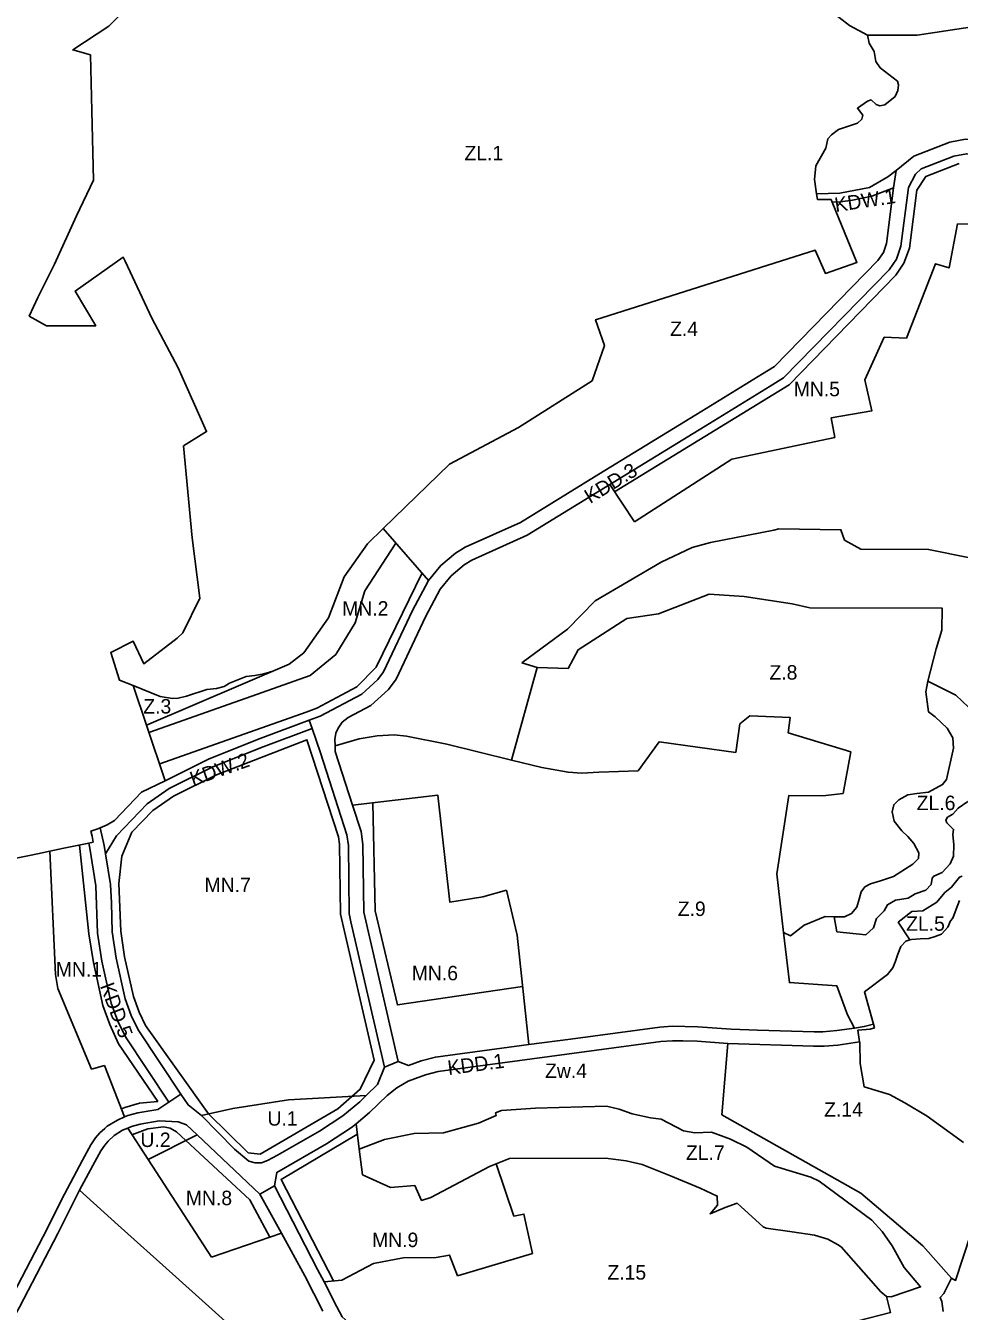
# Model space of a CAD drawing. Extents: x 7425478 to 7427982, y 5538517 to 5541171.
# Drawn here: x 7426136 to 7426780, y 5539827 to 5540715 of the extents above; entities that cross this region are included whole.
import ezdxf

# ---------------------------------------------------------------- set-up
doc = ezdxf.new("R2010")
doc.units = 0
for name, color, linetype in [('linie_rozgraniczajace', 7, 'Continuous'), ('linie_zabudowy_nieprzekraczalne', 7, 'Continuous'), ('oznaczenia_przeznaczen', 7, 'Continuous')]:
    doc.layers.add(name, color=color, linetype=linetype)

msp = doc.modelspace()

# ---------------------------------------------------------------- linework, layer by layer
at = {"layer": 'linie_rozgraniczajace'}
for p, q in [((7426731.05, 5540610.84), (7426736.88, 5540615.14)), ((7426736.88, 5540615.14), (7426735.09, 5540603.21)), ((7426539.11, 5540398.25), (7426556.16, 5540372.49)), ((7426382.66, 5540367.98), (7426413.98, 5540332.1)), ((7426317.69, 5540274.2), (7426219.13, 5540232.16)), ((7426488.83, 5540271.89), (7426471.19, 5540207.93)), ((7426331.51, 5540235.5), (7426333.49, 5540229.81)), ((7426383.59, 5539995.88), (7426392.95, 5539999.8)), ((7426242.88, 5539977.24), (7426234.54, 5539971.71)), ((7426365.94, 5539939.15), (7426363.89, 5539956.79)), ((7426254, 5539949.12), (7426297.44, 5539908.12)), ((7426220.18, 5539932.05), (7426263.89, 5539864.55)), ((7426297.44, 5539908.12), (7426307.41, 5539913.93)), ((7426263.89, 5539864.55), (7426312.26, 5539881.08))]:
    msp.add_line(p, q, dxfattribs=at)
for points in [[(7426717.2, 5540708.68), (7426751.28, 5540708.68), (7426790.92, 5540714.76), (7426810.72, 5540713.06), (7426828.41, 5540705.75), (7426867.84, 5540713.85), (7426908.44, 5540725.51), (7426925.27, 5540731.18), (7426935.28, 5540732.24), (7426974.9, 5540738.42), (7427001.7, 5540742.96), (7427027.17, 5540753.71), (7427042.19, 5540761.09), (7427056.12, 5540769.24), (7427073.04, 5540767.39)], [(7426114.72, 5540137.37), (7426139.34, 5540142.21), (7426147.09, 5540143.92), (7426152.34, 5540145.07), (7426162.05, 5540147.21), (7426179.19, 5540150.67), (7426182.18, 5540151.27), (7426181.63, 5540155.28), (7426180.71, 5540158.94), (7426184.79, 5540160.14), (7426187.14, 5540161.15), (7426191.85, 5540163.18), (7426197.03, 5540166.18), (7426215.67, 5540185.86), (7426232.11, 5540193.68), (7426219.13, 5540232.16), (7426209.94, 5540259.4), (7426200.43, 5540263.25), (7426194.41, 5540282.31), (7426209.98, 5540290), (7426217.22, 5540274.54), (7426240.22, 5540292.2), (7426244.2, 5540295.77), (7426256.04, 5540319.86), (7426250.65, 5540361.46), (7426244.6, 5540424.97), (7426260.61, 5540434.84), (7426241.03, 5540478.97), (7426222.9, 5540513.19), (7426204.34, 5540552.54), (7426202.99, 5540555.41), (7426169.88, 5540531.97), (7426184.03, 5540507.92), (7426150.11, 5540507.96), (7426138.09, 5540514.63), (7426144.07, 5540527.39), (7426155.6, 5540550.57), (7426170.85, 5540583.91), (7426182.53, 5540608.45), (7426181.33, 5540656.47), (7426180.4, 5540695.04), (7426168.21, 5540698.49), (7426193.17, 5540714.88), (7426220.04, 5540742.49)], [(7426621, 5540724.8), (7426690.34, 5540726.34), (7426704.54, 5540715.43), (7426717.2, 5540708.68)], [(7426717.2, 5540708.68), (7426718.28, 5540703.16), (7426721.58, 5540697.31), (7426722.91, 5540690.52), (7426725.83, 5540686.18), (7426737.82, 5540676.86), (7426738.6, 5540674.32), (7426738.02, 5540670.5), (7426736.1, 5540666.31), (7426729.04, 5540660.65), (7426725.66, 5540659.96)], [(7426681.93, 5540599.19), (7426680.54, 5540609.03), (7426681.47, 5540618.54), (7426688.22, 5540630.74), (7426689.69, 5540636.98), (7426692.12, 5540639.96), (7426697.09, 5540643.46), (7426710.13, 5540647.86), (7426713.14, 5540650.73), (7426713.9, 5540653.51), (7426710.17, 5540658.26), (7426717.16, 5540663.2), (7426719.71, 5540663.97), (7426723.13, 5540660.82), (7426725.66, 5540659.96)], [(7426816.94, 5540628.58), (7426806.42, 5540633.45), (7426794.75, 5540636.3), (7426784.82, 5540636.93), (7426773.93, 5540634.87), (7426749.1, 5540625.08), (7426736.88, 5540615.14)], [(7426539.11, 5540398.25), (7426541.43, 5540399.68), (7426607.94, 5540440.48), (7426649.9, 5540466.22), (7426659.15, 5540471.89), (7426732.05, 5540546.65), (7426737.1, 5540553.97), (7426740.18, 5540562.9), (7426745.32, 5540603.54), (7426750.19, 5540612.79), (7426754.12, 5540616.34), (7426776.71, 5540625.22), (7426785.4, 5540626.76), (7426793.22, 5540626.29), (7426803.14, 5540623.95), (7426814.99, 5540618.47), (7426820.42, 5540614.61), (7426825.48, 5540609.63)], [(7426681.93, 5540599.19), (7426697.96, 5540599.45), (7426718.4, 5540603.37), (7426731.05, 5540610.84)], [(7426825.48, 5540609.63), (7426812.98, 5540577.96), (7426779.26, 5540578.26), (7426773.48, 5540547.95), (7426764.01, 5540550.84), (7426743.97, 5540499.31)], [(7426735.09, 5540603.21), (7426730.23, 5540564.71), (7426728.1, 5540558.53), (7426724.3, 5540553.02), (7426652.86, 5540479.76), (7426644.67, 5540474.74), (7426602.71, 5540449), (7426531.43, 5540405.35)], [(7426692.75, 5540593.37), (7426691.9, 5540595.15), (7426682.56, 5540595.15), (7426681.93, 5540599.19)], [(7426692.75, 5540593.37), (7426698.49, 5540593.46), (7426706.73, 5540594.8), (7426720.09, 5540597.59), (7426735.09, 5540603.21)], [(7426476.02, 5540437.68), (7426526.86, 5540469.97), (7426535.4, 5540494.44), (7426529.3, 5540512.1), (7426680.91, 5540560.2), (7426688.01, 5540544.1), (7426709.74, 5540551.68), (7426692.75, 5540593.37)], [(7426743.97, 5540499.31), (7426728.69, 5540500.04), (7426715.14, 5540470.66), (7426720.03, 5540449.11), (7426692.04, 5540444.35), (7426694.47, 5540430.69)], [(7426382.66, 5540367.98), (7426428.37, 5540412.39), (7426476.02, 5540437.68)], [(7426694.47, 5540430.69), (7426623.43, 5540415.8), (7426556.16, 5540372.49)], [(7426531.43, 5540405.35), (7426477.4, 5540372.14), (7426439.1, 5540354.99), (7426432.57, 5540350.95), (7426422.47, 5540342.35), (7426413.98, 5540332.1)], [(7426349.32, 5540217.73), (7426349.12, 5540222.2), (7426349.89, 5540226.48), (7426351.55, 5540230), (7426354.25, 5540234.1), (7426358.49, 5540237.46), (7426374.07, 5540245.76), (7426386.35, 5540256.79), (7426391.48, 5540263.83), (7426411.79, 5540306.93), (7426421.92, 5540326.01), (7426429.61, 5540335.3), (7426438.48, 5540342.84), (7426443.8, 5540346.14), (7426482.08, 5540363.27), (7426539.11, 5540398.25)], [(7426876.56, 5540376.66), (7426815.24, 5540342.11), (7426759.33, 5540353.52), (7426712.55, 5540353.68), (7426701.1, 5540359.93), (7426698.75, 5540367.01), (7426655.83, 5540367.75), (7426652.37, 5540366.73), (7426608.69, 5540358.29), (7426595.99, 5540354.73), (7426574.58, 5540344.68), (7426528.94, 5540317.84), (7426509.87, 5540298.47), (7426478.31, 5540275.12)], [(7426317.69, 5540274.2), (7426327.75, 5540282), (7426344.73, 5540306.26), (7426355.53, 5540334.51), (7426371.82, 5540357.44), (7426382.66, 5540367.98)], [(7426413.98, 5540332.1), (7426413.56, 5540331.59), (7426402.75, 5540311.19), (7426382.84, 5540268.95), (7426378.8, 5540263.58), (7426367.78, 5540253.55), (7426339.15, 5540238.33), (7426331.51, 5540235.5)], [(7426488.83, 5540271.89), (7426510.33, 5540271.12), (7426517.33, 5540284.21), (7426550.85, 5540305.65), (7426572.85, 5540309), (7426607.75, 5540322.65), (7426631.95, 5540320.84), (7426665.02, 5540315.84), (7426677.19, 5540313.17), (7426768.65, 5540312.95), (7426768.37, 5540297.72), (7426764.51, 5540284.7), (7426758.79, 5540262.45)], [(7426209.94, 5540259.4), (7426228.62, 5540251.82), (7426237.16, 5540250.45), (7426241.05, 5540250.8), (7426246.82, 5540252.09), (7426260.8, 5540256.71), (7426267.37, 5540257.34), (7426272.79, 5540258.87), (7426276.45, 5540261.02), (7426288, 5540265.64), (7426293.88, 5540266.29), (7426300.16, 5540267.56), (7426306.37, 5540269.47), (7426317.69, 5540274.2)], [(7426478.31, 5540275.12), (7426488.83, 5540271.89)], [(7426758.79, 5540262.45), (7426757.4, 5540255.05), (7426759.28, 5540241.19), (7426763.85, 5540237.93), (7426772.09, 5540230.09), (7426776.07, 5540223.24), (7426776.38, 5540216.18), (7426771.54, 5540194.56), (7426768.89, 5540191.01), (7426759.29, 5540185.8), (7426751.09, 5540184.91), (7426744.98, 5540183.93), (7426738.79, 5540180.58), (7426735.21, 5540177.09), (7426734.2, 5540172.25), (7426735.6, 5540165.74), (7426740.85, 5540158.98), (7426744.97, 5540155.21), (7426749.02, 5540150.33), (7426752.47, 5540143.84), (7426752.23, 5540140.04), (7426748.51, 5540136.1), (7426734.99, 5540127.56), (7426726.07, 5540124.49), (7426719.09, 5540122.45), (7426715.16, 5540120.35), (7426712.71, 5540117.03), (7426711.32, 5540111.85), (7426709.7, 5540106.43), (7426706.13, 5540101.96), (7426701.11, 5540099.68), (7426694.07, 5540099.6)], [(7426786.93, 5540244.43), (7426778.12, 5540252.72), (7426758.79, 5540262.45)], [(7426232.11, 5540193.68), (7426262.47, 5540208.82), (7426297.58, 5540222.79), (7426331.51, 5540235.5)], [(7426626.08, 5540213.11), (7426628.97, 5540232.89), (7426635.83, 5540238.56), (7426663.77, 5540237.34), (7426662.34, 5540226.66)], [(7426190.73, 5540143.14), (7426198.36, 5540155.68), (7426219.49, 5540177.8), (7426234.79, 5540188.31), (7426264.93, 5540203.34), (7426299.68, 5540217.17), (7426333.49, 5540229.81)], [(7426333.49, 5540229.81), (7426339.24, 5540213.01), (7426357.48, 5540156.31), (7426358.56, 5540148.94), (7426359.17, 5540102.06), (7426360.15, 5540096.27), (7426383.59, 5539995.88)], [(7426659.11, 5540088.9), (7426654.41, 5540129.36), (7426662.86, 5540183.51), (7426686.15, 5540183.25), (7426700.21, 5540184.88), (7426705.54, 5540213.54), (7426662.34, 5540226.66)], [(7426426.51, 5540218.94), (7426398.64, 5540224.49), (7426390.26, 5540225.33), (7426378.48, 5540224.77), (7426366.06, 5540222.71), (7426349.32, 5540217.73)], [(7426349.32, 5540217.73), (7426349.5, 5540213.77), (7426361.42, 5540176.73)], [(7426426.51, 5540218.94), (7426471.19, 5540207.93)], [(7426626.08, 5540213.11), (7426573.14, 5540220.5), (7426558.62, 5540200.41)], [(7426471.19, 5540207.93), (7426492.24, 5540202.74), (7426510.24, 5540199.57), (7426519.84, 5540198.88), (7426531.43, 5540199.51), (7426558.62, 5540200.41)], [(7426361.42, 5540176.73), (7426420.37, 5540183.64), (7426428.5, 5540109.83), (7426451.37, 5540113.45), (7426467.84, 5540118.15)], [(7426361.42, 5540176.73), (7426367.26, 5540158.58), (7426368.55, 5540149.73), (7426369.16, 5540102.96), (7426392.95, 5539999.8)], [(7426694.07, 5540099.6), (7426695.96, 5540089.41), (7426715.91, 5540087.19), (7426721.22, 5540091.99), (7426723.41, 5540098.55), (7426728.6, 5540103.7), (7426730.99, 5540108.03), (7426736.42, 5540111.13), (7426745.19, 5540112.45), (7426749.96, 5540115.46), (7426757.3, 5540118.04), (7426761.14, 5540122.08), (7426761.79, 5540126.47), (7426762.9, 5540127.82), (7426768.59, 5540130.39), (7426774.15, 5540136.35), (7426776.51, 5540141.63), (7426776.76, 5540149.3), (7426775.96, 5540156.6), (7426776.56, 5540160.11), (7426771.84, 5540164.51), (7426771.22, 5540166.4), (7426772.23, 5540168.44), (7426776.07, 5540170.69), (7426779.66, 5540174.68), (7426786.36, 5540179.24)], [(7426187.14, 5540161.15), (7426189.79, 5540149), (7426190.73, 5540143.14)], [(7426179.19, 5540150.67), (7426179.96, 5540147.14), (7426184.19, 5540121.01), (7426185.21, 5540088.4), (7426188.29, 5540069.14), (7426194.77, 5540040.12), (7426199.34, 5540027.54), (7426204.68, 5540016.71), (7426234.54, 5539971.71)], [(7426152.34, 5540145.07), (7426156.19, 5540059.74), (7426157.81, 5540050.14), (7426181.16, 5539994.47), (7426190.06, 5539996.87), (7426204.01, 5539961.42)], [(7426190.73, 5540143.14), (7426194.14, 5540122.1), (7426194.87, 5540109.33), (7426195.3, 5540089.29), (7426198.12, 5540071.02), (7426204.39, 5540042.93), (7426208.57, 5540031.43), (7426213.29, 5540021.63), (7426242.88, 5539977.24)], [(7426746.25, 5540083.73), (7426738.37, 5540095.96), (7426747.68, 5540103.35), (7426755.24, 5540103.81), (7426764.91, 5540109.86), (7426770.52, 5540116.42), (7426775.13, 5540120.09), (7426780.59, 5540127.08), (7426782.46, 5540127.73)], [(7426475.03, 5540087.02), (7426467.84, 5540118.15)], [(7426780.53, 5540110.98), (7426778.31, 5540104.9), (7426776.1, 5540098.83), (7426774.41, 5540096.87), (7426772.54, 5540092.44), (7426768.28, 5540087.61), (7426763.87, 5540086.14), (7426759.46, 5540084.66), (7426753.5, 5540084.38), (7426747.54, 5540084.1), (7426746.25, 5540083.73), (7426743.58, 5540082.96), (7426740.15, 5540079.11), (7426738.14, 5540073.83), (7426736.34, 5540069.08), (7426734.53, 5540064.34), (7426730.96, 5540059.83), (7426715.01, 5540047.76), (7426721.14, 5540025.56), (7426721.87, 5540022.91), (7426718.97, 5540022.01), (7426710.5, 5540021.4), (7426711.64, 5540013.23), (7426711.73, 5540012.6), (7426712.07, 5539998.44), (7426714.67, 5539982.3), (7426732.25, 5539976.93), (7426742.97, 5539971.2), (7426758.36, 5539961.98), (7426783.48, 5539943.79)], [(7426659.11, 5540088.9), (7426664.01, 5540086.51), (7426673.35, 5540093.92), (7426687.84, 5540099.88), (7426694.07, 5540099.6)], [(7426483.12, 5540011.39), (7426475.03, 5540087.02)], [(7426708.01, 5540022.82), (7426703.35, 5540032.05), (7426695.86, 5540052.07), (7426663.14, 5540054.25), (7426659.11, 5540088.9)], [(7426708.01, 5540022.82), (7426695.8, 5540021.05), (7426686.3, 5540020.31), (7426680.18, 5540020.24), (7426641.21, 5540021.45), (7426622.92, 5540022.02), (7426599.97, 5540023.75), (7426582.06, 5540024.11), (7426573.76, 5540023.53), (7426511.97, 5540015.25), (7426483.12, 5540011.39)], [(7426708.01, 5540022.82), (7426714.85, 5540023.8), (7426721.14, 5540025.56)], [(7426620.66, 5540012.17), (7426599.5, 5540013.86), (7426589.56, 5540013.96), (7426582.31, 5540014.11), (7426574.46, 5540013.56), (7426420.64, 5539992.93), (7426411.78, 5539990.57), (7426399.79, 5539986.26), (7426391.94, 5539981.61), (7426385.28, 5539976.36), (7426373.11, 5539964.44), (7426363.89, 5539956.79)], [(7426620.66, 5540012.17), (7426679.87, 5540010.25), (7426687.08, 5540010.34), (7426696.64, 5540011.09), (7426711.64, 5540013.23)], [(7426392.95, 5539999.8), (7426400.11, 5539997), (7426408.8, 5540000.12), (7426418.68, 5540002.75), (7426483.12, 5540011.39)], [(7426775.14, 5539850.04), (7426755.35, 5539872.34), (7426712.53, 5539908.71), (7426616.48, 5539962.94), (7426620.66, 5540012.17)], [(7426383.59, 5539995.88), (7426378.67, 5539983.88), (7426370.9, 5539976.28)], [(7426234.54, 5539971.71), (7426226.91, 5539966.54), (7426213.06, 5539964.26), (7426206.17, 5539962.34), (7426204.01, 5539961.42)], [(7426257.18, 5539962.39), (7426247.91, 5539969.69), (7426242.88, 5539977.24)], [(7426257.18, 5539962.39), (7426278.82, 5539967.23), (7426317.07, 5539973.35), (7426370.9, 5539976.28)], [(7426370.9, 5539976.28), (7426366.4, 5539971.87), (7426354.75, 5539962.19), (7426338.55, 5539951.51), (7426309.68, 5539935.03), (7426302.75, 5539931.29), (7426298.54, 5539929.82), (7426294.07, 5539929.79), (7426289.74, 5539930.88), (7426279.87, 5539939.17), (7426257.18, 5539962.39)], [(7426730.15, 5539837.31), (7426733.53, 5539837.14), (7426753.78, 5539844.06), (7426742.35, 5539857.36), (7426734.03, 5539872.41), (7426727.15, 5539882.39), (7426720.01, 5539890.12), (7426683.71, 5539917.05), (7426677.85, 5539919.86), (7426652.8, 5539927.48), (7426633.86, 5539940.56), (7426622.47, 5539946.19), (7426609.25, 5539951.02), (7426597.85, 5539950.45), (7426590.04, 5539951.75), (7426574.49, 5539959.84), (7426567.24, 5539960.82), (7426554.49, 5539963.5), (7426545.58, 5539966.92), (7426536.85, 5539968.81), (7426487.8, 5539967.5), (7426464.34, 5539965.93), (7426460.23, 5539964.2), (7426460.7, 5539962.46), (7426448.32, 5539957.18), (7426424.27, 5539950.4), (7426403.96, 5539949.92), (7426383.58, 5539945.97), (7426365.94, 5539939.15)], [(7426204.01, 5539961.42), (7426198.99, 5539959.27), (7426192.04, 5539954.96), (7426190.44, 5539953.51)], [(7426190.44, 5539953.51), (7426186.95, 5539950.37), (7426183.98, 5539946.92), (7426180.68, 5539942.27), (7426174.89, 5539931.6), (7426162.52, 5539908.13), (7426159.34, 5539901.8)], [(7426206.19, 5539953.65), (7426202.64, 5539952.24), (7426196.8, 5539948.62), (7426192.68, 5539944.76), (7426190.28, 5539941.98), (7426187.48, 5539938.04), (7426181.94, 5539927.82), (7426172.93, 5539910.75)], [(7426206.19, 5539953.65), (7426208.83, 5539954.77), (7426214.82, 5539956.45), (7426227.97, 5539958.7), (7426241.03, 5539958.1), (7426246.7, 5539955.97), (7426254, 5539949.12)], [(7426206.19, 5539953.65), (7426220.18, 5539932.05)], [(7426307.41, 5539913.93), (7426309.06, 5539923.16), (7426343.52, 5539942.84), (7426360.71, 5539954.14), (7426363.89, 5539956.79)], [(7426220.18, 5539932.05), (7426254, 5539949.12)], [(7426365.94, 5539939.15), (7426368.31, 5539921.53), (7426387.64, 5539912.62), (7426404.45, 5539914.05), (7426409.15, 5539903.77), (7426415.6, 5539905.73), (7426455.97, 5539927.28), (7426460.7, 5539929.11)], [(7426730.15, 5539837.31), (7426726.41, 5539840.54), (7426698.92, 5539871.65), (7426696.41, 5539873.44), (7426689.79, 5539877.12), (7426680.39, 5539879.83), (7426665.12, 5539881.98), (7426647.1, 5539884.51), (7426645.07, 5539885.5), (7426626.99, 5539901.8), (7426618.67, 5539898.87), (7426608.34, 5539894.53), (7426613.47, 5539900.46), (7426613.35, 5539906.75), (7426601.6, 5539912.15), (7426581.08, 5539920.81), (7426561.53, 5539928.63), (7426550.29, 5539931.19), (7426536.23, 5539933.02), (7426469.9, 5539932.65), (7426460.7, 5539929.11)], [(7426472.76, 5539892.84), (7426460.7, 5539929.11)], [(7426172.93, 5539910.75), (7426157.78, 5539880.88), (7426131.38, 5539829.96), (7426120.78, 5539811.26), (7426109.12, 5539796.88), (7426076.6, 5539761.74), (7426068.87, 5539756.4), (7426052.03, 5539754.96), (7426040.49, 5539757.6), (7426024.63, 5539763.12), (7426003.8, 5539773.22), (7425997.61, 5539775.55), (7425990.1, 5539777.21), (7425982.57, 5539778.07)], [(7426172.93, 5539910.75), (7426199.52, 5539886.77), (7426237.04, 5539852.97), (7426285, 5539810.09)], [(7426297.44, 5539908.12), (7426312.26, 5539881.08)], [(7426307.41, 5539913.93), (7426337.31, 5539856.17), (7426341.76, 5539847.53)], [(7425861.28, 5539789.58), (7425876.14, 5539788.48), (7425917.05, 5539790.68), (7425930.12, 5539791.21), (7425946.2, 5539790.43), (7425991.44, 5539785.11), (7425999.89, 5539783.23), (7426006.95, 5539780.58), (7426027.7, 5539770.52), (7426042.71, 5539765.3), (7426052.59, 5539763.04), (7426066.07, 5539764.19), (7426071.32, 5539767.83), (7426103.07, 5539802.12), (7426114.14, 5539815.78), (7426124.35, 5539833.77), (7426150.65, 5539884.52), (7426159.34, 5539901.8)], [(7426433.95, 5539851.74), (7426485.62, 5539867.17), (7426479.74, 5539894.35), (7426472.76, 5539892.84)], [(7426312.26, 5539881.08), (7426328.42, 5539851.59), (7426341, 5539827.19)], [(7426788.38, 5539880.66), (7426777.89, 5539848.46), (7426775.14, 5539850.04), (7426769.82, 5539839.5), (7426767.19, 5539836.75), (7426768.52, 5539834.05), (7426769.46, 5539826.99)], [(7426433.95, 5539851.74), (7426428.35, 5539866.05), (7426419.12, 5539864.37), (7426396.42, 5539864.16), (7426375.91, 5539860.18), (7426354.01, 5539848.67), (7426341.76, 5539847.53)], [(7426341.76, 5539847.53), (7426350.65, 5539830.3), (7426354.22, 5539823.36), (7426360.39, 5539817.82), (7426382.72, 5539807.31), (7426387.89, 5539805.46), (7426392.07, 5539804.68), (7426406.6, 5539801.94), (7426417.95, 5539798.68), (7426428.88, 5539791.94), (7426435.25, 5539784.9), (7426444.81, 5539772.3)], [(7426566.31, 5539790.94), (7426585.56, 5539801.43), (7426621.44, 5539806.39), (7426651.66, 5539810.88), (7426672.2, 5539814.35), (7426709.79, 5539820.37), (7426732.96, 5539826.26), (7426730.15, 5539837.31)]]:
    msp.add_lwpolyline(points, dxfattribs=at)
at = {"layer": 'linie_zabudowy_nieprzekraczalne'}
for p, q in [((7426208.97, 5540158.1), (7426202.06, 5540141.48)), ((7426219.96, 5539953.2), (7426209.08, 5539949.19))]:
    msp.add_line(p, q, dxfattribs=at)
for points in [[(7426780.48, 5540620.13), (7426757.33, 5540611.15), (7426751.14, 5540601.71), (7426746.06, 5540561.53), (7426742.15, 5540551.19), (7426736.71, 5540542.83), (7426662.92, 5540467.17), (7426542.42, 5540393.25)], [(7426391.38, 5540357.75), (7426369.89, 5540324.97), (7426363.3, 5540302.67), (7426349.95, 5540280.95), (7426332.06, 5540266.3), (7426287.87, 5540250.73), (7426220.83, 5540227.1)], [(7426228.38, 5540205.25), (7426228.38, 5540205.25), (7426329.41, 5540241.12), (7426336.69, 5540243.81), (7426364.3, 5540258.5), (7426377.67, 5540272.07), (7426409.42, 5540337.28)], [(7426202.06, 5540141.48), (7426200.11, 5540122.75), (7426201.29, 5540089.81), (7426204.02, 5540072.13), (7426210.16, 5540044.62), (7426214.1, 5540033.76), (7426218.52, 5540024.61), (7426261.84, 5539963.5), (7426289.26, 5539936.72), (7426297.5, 5539935.82), (7426351.17, 5539967.02), (7426366.7, 5539980.56), (7426376.4, 5540000.56), (7426353.18, 5540101.52), (7426352.43, 5540149.76), (7426351.62, 5540154.95), (7426329.89, 5540222.03), (7426267.38, 5540197.86), (7426237.84, 5540183.13), (7426223.4, 5540173.21), (7426208.97, 5540158.1)], [(7426375.4, 5540178.37), (7426377.15, 5540103.92), (7426392.37, 5540038.88), (7426478.83, 5540051.5)], [(7426226.96, 5539972.19), (7426199.85, 5540011.87), (7426193.81, 5540025.19), (7426189, 5540038.44), (7426182.4, 5540068.01), (7426179.23, 5540087.83), (7426172.73, 5540149.28)], [(7426201.81, 5539967), (7426204.18, 5539968.01), (7426214.35, 5539970.88), (7426226.96, 5539972.19)], [(7426304.3, 5539878.36), (7426290.42, 5539904.28), (7426239.87, 5539951.26), (7426235.48, 5539953.66), (7426230.9, 5539954.51), (7426219.96, 5539953.2)], [(7426364.29, 5539949.31), (7426312.07, 5539918.3), (7426348.21, 5539848.13)]]:
    msp.add_lwpolyline(points, dxfattribs=at)

# ---------------------------------------------------------------- texts
at = {"layer": 'oznaczenia_przeznaczen'}
for s, p in [('ZL.1', (7426438.71, 5540622.24)), ('Z.4', (7426580.72, 5540500.9)), ('MN.5', (7426666.13, 5540459.25)), ('MN.2', (7426354.26, 5540307.72)), ('Z.8', (7426649.36, 5540263.51)), ('Z.3', (7426216.87, 5540240.12)), ('ZL.6', (7426751.06, 5540173.39)), ('MN.7', (7426259.22, 5540116.71)), ('Z.9', (7426586.02, 5540100.23)), ('ZL.5', (7426743.77, 5540090.02)), ('MN.1', (7426156.49, 5540058.45)), ('MN.6', (7426402.32, 5540055.83)), ('Zw.4', (7426494.37, 5539988.34)), ('Z.14', (7426687.12, 5539961.59)), ('U.1', (7426302.7, 5539955.42)), ('U.2', (7426214.92, 5539940.66)), ('ZL.7', (7426591.66, 5539931.72)), ('MN.8', (7426246.28, 5539900.49)), ('MN.9', (7426374.87, 5539871.52)), ('Z.15', (7426537.44, 5539849.07))]:
    msp.add_text(s, height=10, dxfattribs=at).set_placement(p)
for s, rotation, p in [('KDW.1', 8.69998, (7426695.17, 5540586.44)), ('KDD.3', 31.32903, (7426525.5, 5540384.83)), ('KDW.2', 19.41093, (7426251.23, 5540189.82)), ('KDD.5', 290.50239, (7426186.83, 5540051.95)), ('KDD.1', 7.48155, (7426427.73, 5539990.36))]:
    msp.add_text(s, height=10, rotation=rotation, dxfattribs=at).set_placement(p)

doc.saveas('drawing.dxf')
